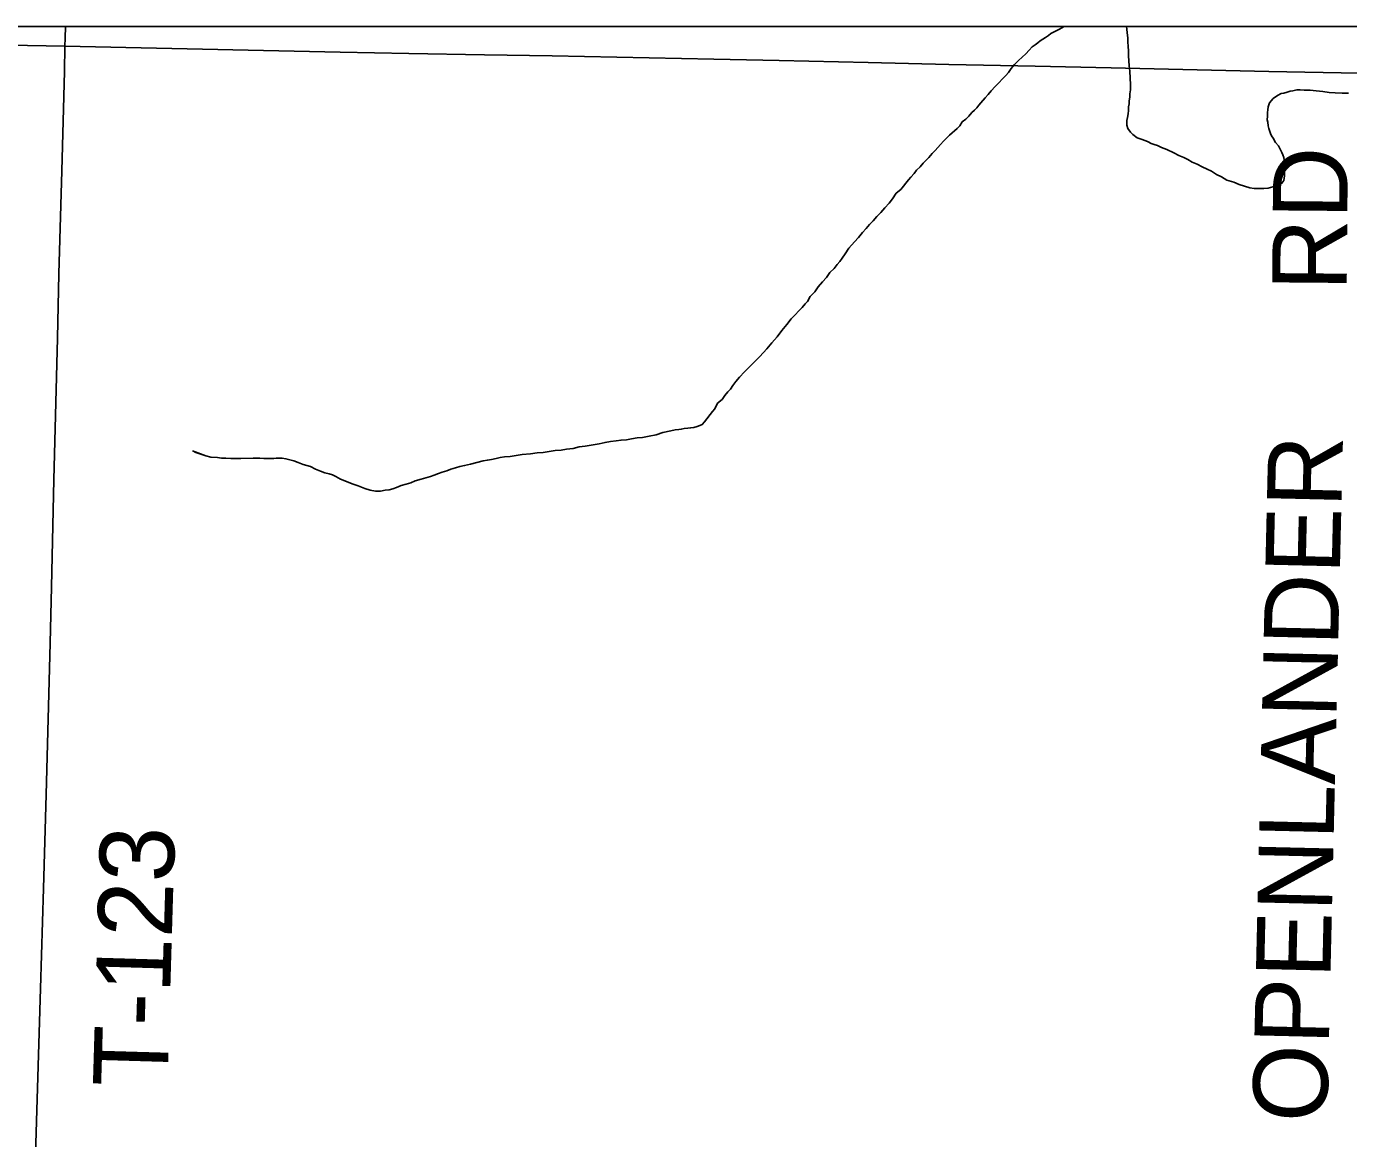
# Model space of a CAD drawing. Extents: x 0 to 64.8, y -5 to 22.
# Drawn here: x 3.754 to 4.761, y 20.052 to 20.9 of the extents above; entities that cross this region are included whole.
import ezdxf

# ---------------------------------------------------------------- set-up
doc = ezdxf.new("R2010")
doc.units = 0
for name, color, linetype in [('GM_X_Adjacent_County', 7, 'Continuous'), ('GM_X_County', 7, 'Continuous'), ('GM_X_County_Road', 7, 'Continuous'), ('GM_X_Minor_River', 7, 'Continuous'), ('GM_X_Township', 7, 'Continuous'), ('GM_X_Township_Road', 7, 'Continuous'), ('GM_X_Township_Road_Text', 7, 'Continuous'), ('SH_Data', 7, 'Continuous')]:
    doc.layers.add(name, color=color, linetype=linetype)

msp = doc.modelspace()

# ---------------------------------------------------------------- linework, layer by layer
at = {"layer": 'GM_X_Adjacent_County'}
msp.add_lwpolyline([(8.9, 19.781), (8.9, 20.9), (2.1, 20.9), (2.1, 19.9176)], dxfattribs=at)
at = {"layer": 'GM_X_County'}
msp.add_lwpolyline([(8.9, 19.781), (8.9, 20.9), (2.1, 20.9), (2.1, 19.9176)], dxfattribs=at)
at = {"layer": 'GM_X_County_Road'}
for points in [[(3.0661, 20.9), (3.1178, 20.8989), (3.2377, 20.8961), (3.316, 20.8946), (3.3981, 20.8929), (3.4397, 20.8919), (3.4864, 20.8911), (3.6504, 20.8875), (3.6778, 20.8868), (3.7549, 20.8855), (3.7833, 20.885)], [(3.7833, 20.885), (3.9463, 20.8814), (3.9929, 20.8804), (4.0452, 20.8794), (4.103, 20.8784), (4.1546, 20.8775), (4.2776, 20.875), (4.3274, 20.8739), (4.3951, 20.8725), (4.4566, 20.8711), (4.5225, 20.8698), (4.5803, 20.8684), (4.7003, 20.8657), (4.7693, 20.8644), (4.7847, 20.8641)]]:
    msp.add_lwpolyline(points, dxfattribs=at)
at = {"layer": 'GM_X_Minor_River'}
for points in [[(4.5283, 20.8904), (4.5302, 20.8915), (4.5325, 20.893), (4.5344, 20.8945), (4.5409, 20.8978), (4.5445, 20.9)], [(4.592, 20.9), (4.5923, 20.8978), (4.5926, 20.8951), (4.5929, 20.8913), (4.5929, 20.8882), (4.5932, 20.8848), (4.5936, 20.8814), (4.5935, 20.8776), (4.5938, 20.8738), (4.5941, 20.87), (4.5944, 20.8658), (4.5951, 20.8555), (4.595, 20.8517), (4.5946, 20.8487), (4.5945, 20.846), (4.5941, 20.8434), (4.5941, 20.8411), (4.5936, 20.8388), (4.5936, 20.8358), (4.5932, 20.8335), (4.5928, 20.8305), (4.5923, 20.8282), (4.5923, 20.8248), (4.593, 20.8221), (4.5949, 20.8194), (4.5967, 20.8175), (4.6001, 20.8152), (4.6031, 20.814), (4.6066, 20.8128), (4.6084, 20.812), (4.6107, 20.8108), (4.613, 20.81), (4.6156, 20.8092), (4.6186, 20.8077), (4.6228, 20.8061), (4.6281, 20.8037), (4.6319, 20.8017), (4.6356, 20.8002), (4.6387, 20.7986), (4.6421, 20.7966), (4.6458, 20.7951), (4.6496, 20.7931), (4.6534, 20.7911), (4.6568, 20.7896), (4.6605, 20.7872), (4.6643, 20.7853), (4.6685, 20.7829), (4.6738, 20.7813), (4.6779, 20.7794), (4.6859, 20.7769), (4.6893, 20.7765), (4.6912, 20.7765), (4.6938, 20.7764), (4.6965, 20.7764), (4.6999, 20.7767), (4.7034, 20.7778), (4.7057, 20.7782), (4.7076, 20.7789), (4.7103, 20.7804), (4.7118, 20.7826), (4.7123, 20.786), (4.7123, 20.7887), (4.7124, 20.7921), (4.7124, 20.7948), (4.7124, 20.7967), (4.7117, 20.8001), (4.711, 20.802), (4.7103, 20.8039), (4.7088, 20.807), (4.7077, 20.8089), (4.7054, 20.8116), (4.7036, 20.8147), (4.7025, 20.8166), (4.7017, 20.8185), (4.7003, 20.8223), (4.6999, 20.8242)], [(4.2623, 20.5944), (4.265, 20.5951), (4.2669, 20.5959), (4.2688, 20.5966), (4.2704, 20.5985), (4.2766, 20.6064), (4.2785, 20.6086), (4.2805, 20.6128), (4.284, 20.6157), (4.2859, 20.6187), (4.2882, 20.6214), (4.2902, 20.6236), (4.2921, 20.6262), (4.2944, 20.6293), (4.2972, 20.6326), (4.301, 20.6367), (4.3049, 20.6405), (4.3088, 20.6446), (4.3126, 20.6483), (4.318, 20.6543), (4.3219, 20.6588), (4.3258, 20.6633), (4.3293, 20.6682), (4.3332, 20.6727), (4.3366, 20.6772), (4.3397, 20.6802), (4.3424, 20.6832), (4.3448, 20.6858), (4.3471, 20.6885), (4.349, 20.6903), (4.351, 20.6941), (4.3545, 20.6978), (4.3572, 20.7016), (4.3603, 20.7053), (4.3634, 20.7087), (4.3661, 20.7125), (4.3692, 20.7155), (4.3715, 20.7185), (4.3735, 20.7207), (4.3754, 20.7233), (4.3777, 20.7267), (4.3805, 20.7309), (4.3847, 20.7357), (4.3878, 20.7391), (4.3909, 20.7429), (4.3936, 20.7459), (4.3963, 20.7489), (4.3991, 20.7519), (4.4018, 20.7552), (4.4049, 20.7582), (4.408, 20.7616), (4.4111, 20.7653), (4.4138, 20.7687), (4.4165, 20.7729), (4.42, 20.7758), (4.4258, 20.783), (4.4277, 20.7852), (4.4301, 20.7878), (4.432, 20.7905), (4.4347, 20.7931), (4.437, 20.7957), (4.4393, 20.798), (4.4413, 20.8002), (4.444, 20.8032), (4.4463, 20.8054), (4.4482, 20.8077), (4.4502, 20.8099), (4.4525, 20.8126), (4.4548, 20.8148), (4.4571, 20.8171), (4.4591, 20.8189), (4.461, 20.8204), (4.4629, 20.8223), (4.4649, 20.8242), (4.4668, 20.8272), (4.4695, 20.8294), (4.4718, 20.8316), (4.4741, 20.8343), (4.4761, 20.8361), (4.478, 20.838), (4.4796, 20.8399), (4.4811, 20.8418), (4.4842, 20.8455), (4.4865, 20.8481), (4.4889, 20.8508), (4.4919, 20.8541), (4.4947, 20.8571), (4.4974, 20.8601), (4.5001, 20.8627), (4.502, 20.865), (4.504, 20.868), (4.5067, 20.871), (4.5098, 20.874), (4.5125, 20.8766), (4.5152, 20.8792), (4.5179, 20.8818), (4.5202, 20.8845), (4.5225, 20.8859), (4.5244, 20.8874), (4.5263, 20.8889), (4.5283, 20.8904)], [(4.6999, 20.8242), (4.6996, 20.8269), (4.6992, 20.8288), (4.6993, 20.8315), (4.6993, 20.8345), (4.6997, 20.8364), (4.6998, 20.8387), (4.701, 20.8417), (4.7037, 20.8451), (4.7071, 20.8473), (4.7098, 20.8488), (4.7117, 20.8491), (4.7144, 20.8498), (4.7167, 20.8506), (4.7186, 20.8509), (4.7217, 20.8516), (4.7243, 20.8516), (4.7274, 20.8515), (4.7319, 20.8515), (4.7365, 20.851), (4.7414, 20.8505), (4.7463, 20.8497), (4.7509, 20.8493), (4.7562, 20.8492), (4.7612, 20.8491)], [(3.8805, 20.5765), (3.8907, 20.5726), (3.8824, 20.5754), (3.8907, 20.5726), (3.8945, 20.5717), (3.8995, 20.5713), (3.9025, 20.5709), (3.9059, 20.5708), (3.9097, 20.5707), (3.9135, 20.5707), (3.9173, 20.5706), (3.9268, 20.5709), (3.9291, 20.5708), (3.9318, 20.5708), (3.9348, 20.5707), (3.9375, 20.5707), (3.9402, 20.5706), (3.9424, 20.5706), (3.9443, 20.571), (3.9466, 20.5709), (3.9489, 20.5709), (3.9516, 20.5705), (3.9546, 20.5697), (3.9576, 20.5688), (3.961, 20.5676), (3.9648, 20.5661), (3.9705, 20.5645), (3.9743, 20.5625), (3.978, 20.5609), (3.9814, 20.5597), (3.9845, 20.5589), (3.9871, 20.5581), (3.9898, 20.5569), (3.9932, 20.555), (3.9977, 20.553), (4.0022, 20.5514), (4.0068, 20.5498), (4.0117, 20.5478), (4.0159, 20.5466), (4.02, 20.5458), (4.0238, 20.5458), (4.0273, 20.5465), (4.0303, 20.5468), (4.033, 20.5475), (4.036, 20.5486), (4.0395, 20.5501), (4.0433, 20.5511), (4.0468, 20.5522), (4.0502, 20.5537), (4.0548, 20.5548), (4.0582, 20.5558), (4.0617, 20.5569), (4.0647, 20.558), (4.0678, 20.5591), (4.0708, 20.5602), (4.0743, 20.5613), (4.0773, 20.5624), (4.0808, 20.5635), (4.0842, 20.5646), (4.0877, 20.5653), (4.0922, 20.5663), (4.1018, 20.5688), (4.1052, 20.5695), (4.1083, 20.5699), (4.1117, 20.5706), (4.1148, 20.5713), (4.1182, 20.572), (4.1224, 20.5723), (4.127, 20.573), (4.1315, 20.5737), (4.138, 20.5743), (4.143, 20.575), (4.1475, 20.5753), (4.1521, 20.576), (4.1567, 20.5767), (4.1613, 20.577), (4.1654, 20.5777), (4.1704, 20.5784), (4.175, 20.5795), (4.1796, 20.5801), (4.1841, 20.5808), (4.1902, 20.5819), (4.1948, 20.5829), (4.199, 20.5836), (4.2032, 20.584), (4.207, 20.5847), (4.2112, 20.585), (4.215, 20.5857), (4.2192, 20.5864), (4.2234, 20.5867), (4.2284, 20.5877), (4.2337, 20.5888), (4.2387, 20.5906), (4.2448, 20.5917), (4.2482, 20.5924), (4.2509, 20.5927), (4.2528, 20.593), (4.2551, 20.5934), (4.2577, 20.5937), (4.26, 20.5941), (4.2623, 20.5944)]]:
    msp.add_lwpolyline(points, dxfattribs=at)
at = {"layer": 'GM_X_Township'}
msp.add_lwpolyline([(5.7946, 20.9), (2.1, 20.9), (2.1, 19.9176)], dxfattribs=at)
at = {"layer": 'GM_X_Township_Road'}
for points in [[(3.7833, 20.885), (3.7835, 20.8911), (3.7838, 20.9)], [(3.7551, 19.8875), (3.7573, 19.9203), (3.76, 20.0063), (3.7648, 20.1666), (3.767, 20.243), (3.769, 20.3145), (3.772, 20.43), (3.7731, 20.4729), (3.7749, 20.5543), (3.7776, 20.6624), (3.7788, 20.7115), (3.7809, 20.7898), (3.7829, 20.8656), (3.7833, 20.885)]]:
    msp.add_lwpolyline(points, dxfattribs=at)
at = {"layer": 'SH_Data'}
msp.add_line((2.1, 20.9), (8.9, 20.9), dxfattribs=at)

# ---------------------------------------------------------------- texts
at = {"layer": 'GM_X_Township_Road_Text'}
for s, rotation, p in [('RD', 89.5059, (4.7597, 20.6982)), ('OPENLANDER', 88.663, (4.7447, 20.0643)), ('T-123', 88.317, (3.8614, 20.091))]:
    msp.add_text(s, height=0.05682, rotation=rotation, dxfattribs=at).set_placement(p)

doc.saveas('drawing.dxf')
